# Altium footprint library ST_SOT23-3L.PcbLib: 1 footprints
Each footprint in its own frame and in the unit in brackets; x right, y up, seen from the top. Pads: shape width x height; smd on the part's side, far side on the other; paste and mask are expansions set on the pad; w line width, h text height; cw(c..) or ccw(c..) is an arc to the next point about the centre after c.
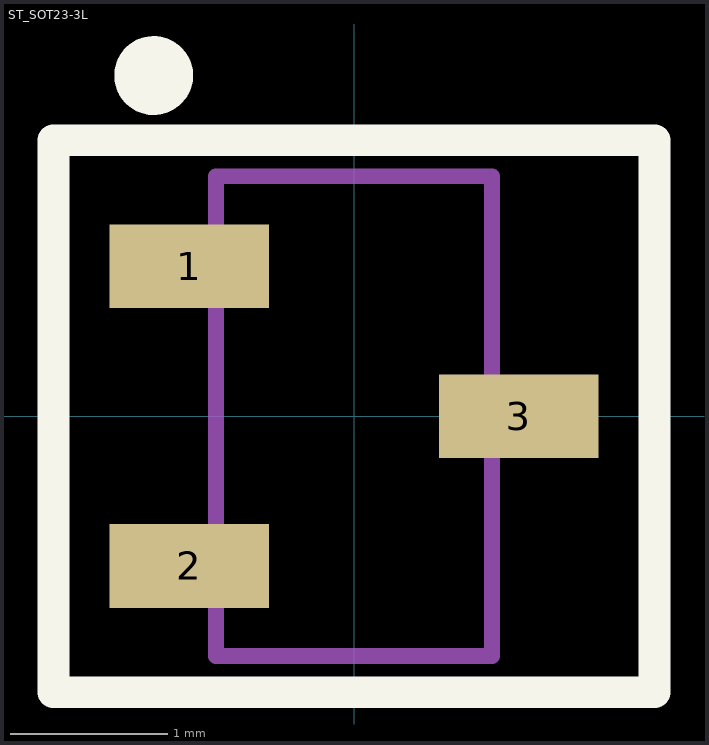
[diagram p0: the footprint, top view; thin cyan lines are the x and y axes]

## ST_SOT23-3L [mm]
height 1.25
pads (3):
  rect 1.01x0.53 smd: 1(-1.045,0.95) 2(-1.045,-0.95) 3(1.045,0)
Top Overlay:
  circle w0.25: c-1.27,2.159 r0.125
  lines w0.2: -1.905,-1.75 1.905,-1.75 1.905,1.75 -1.905,1.75 -1.905,-1.75
Mechanical 13:
  lines w0.1: -0.875,-1.52 0.875,-1.52 0.875,1.52 -0.875,1.52 -0.875,-1.52
3D body "ST_SOT23-3L.STEP": height 1.17, standoff 0, extent -1.4,-1.462 1.4,1.462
